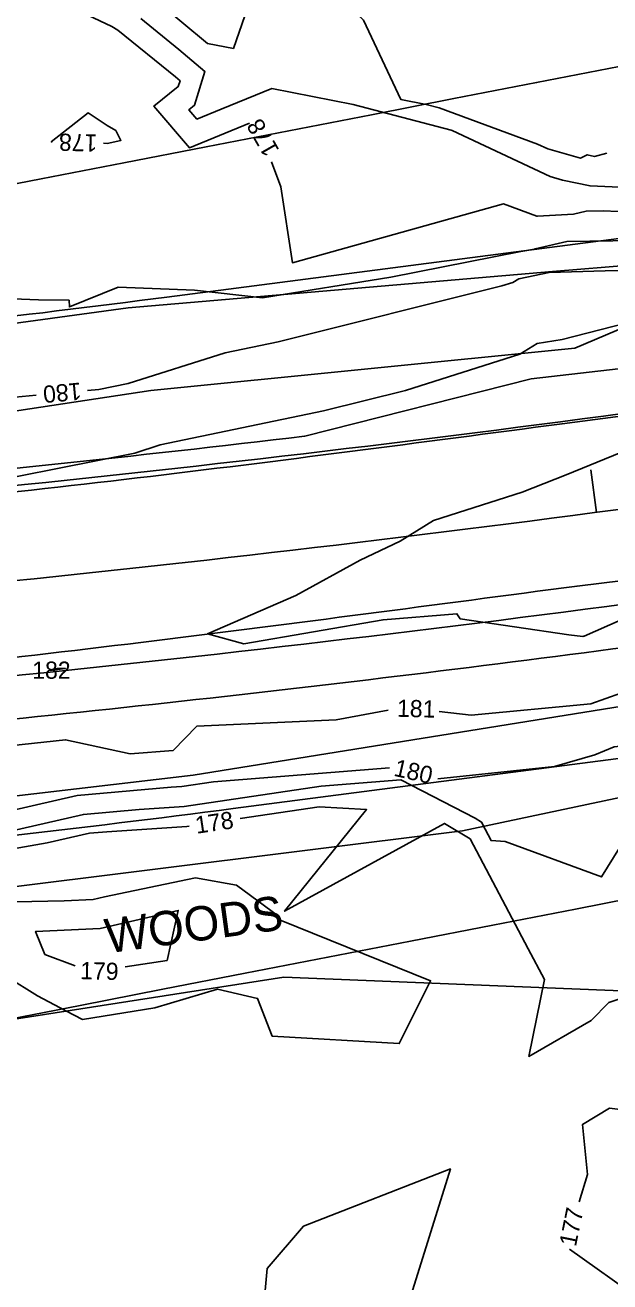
# Model space of a CAD drawing. Extents: x 2086416 to 2115205, y 575507 to 632762.
# Drawn here: x 2111355.3 to 2111423.3, y 581547.6 to 581693.8 of the extents above; entities that cross this region are included whole.
import ezdxf

# ---------------------------------------------------------------- set-up
doc = ezdxf.new("R2010")
doc.units = 0
for name, color, linetype in [('DTM Contours Major', 7, 'Continuous'), ('DTM Contours Major Text', 7, 'Continuous'), ('DTM Contours Minor', 7, 'Continuous'), ('DTM Contours Minor Text', 7, 'Continuous'), ('Exist Hydrographic FEMA Cross Section', 7, 'Continuous'), ('Exist Right of Way Line', 7, 'Continuous'), ('Exist Roads EOP', 7, 'Continuous'), ('Exist Vegetation Woods Line', 7, 'Continuous'), ('Exist Vegetation Woods Line Text', 7, 'Continuous'), ('Prop EOT', 7, 'Continuous'), ('Prop Horizontal Alignment', 7, 'Continuous'), ('Prop Horizontal Alignment Tick Small', 7, 'Continuous'), ('Prop Paved Shoulder', 7, 'Continuous'), ('Prop SS Fill Line', 7, 'Continuous')]:
    doc.layers.add(name, color=color, linetype=linetype)

msp = doc.modelspace()

# ---------------------------------------------------------------- linework, layer by layer
at = {"layer": 'DTM Contours Major'}
for points in [[(2111362.56, 581651.3), (2111363.86, 581651.42), (2111367.3, 581652.1), (2111378.59, 581655.68), (2111384.74, 581656.96), (2111410.78, 581663.46), (2111412.04, 581663.86), (2111412.76, 581664.3), (2111416.28, 581665.01), (2111422.79, 581665.2), (2111444.21, 581665.52), (2111445.08, 581665.48), (2111446.41, 581665.36), (2111460.73, 581665.47)], [(2111261.76, 581634.8), (2111264.49, 581635.02), (2111269.8, 581635.25), (2111274.63, 581635.79), (2111286.36, 581637), (2111296.9, 581639.48), (2111308.95, 581641.32), (2111310.89, 581644.07), (2111316.03, 581645.06), (2111318.27, 581646.08), (2111327.46, 581646.18), (2111327.64, 581649.21), (2111352.5, 581650.37), (2111356.59, 581650.74)], [(2111501.47, 581623.56), (2111493.7, 581622.18), (2111485.5, 581619.95), (2111473.32, 581616.45), (2111470.82, 581616.07), (2111467.71, 581615.67), (2111457.92, 581614.37), (2111451.07, 581613.49), (2111428.1, 581610.45), (2111427.71, 581610.26), (2111423.84, 581609.83), (2111421.6, 581608.92), (2111416.91, 581607.54), (2111403.3, 581606.12)], [(2111397.68, 581607.39), (2111377.21, 581605.77), (2111373.52, 581605.22), (2111372.31, 581605.14), (2111361.36, 581604.17), (2111347.99, 581601.11), (2111339.17, 581600.17), (2111336.15, 581600.07), (2111333.7, 581599.12), (2111322.16, 581599.48), (2111304, 581596.49), (2111303.23, 581596.59), (2111302.72, 581596.56), (2111299.03, 581595.67), (2111298.77, 581595.63)]]:
    msp.add_lwpolyline(points, dxfattribs=at)
at = {"layer": 'DTM Contours Minor'}
for points in [[(2111260.91, 581756.14), (2111260.56, 581753.66), (2111263.25, 581749.57), (2111272.06, 581734.37), (2111271.17, 581754.63), (2111289.23, 581762.28), (2111298.09, 581762.28), (2111340.41, 581719.17), (2111341.02, 581718.36), (2111341.03, 581718.18), (2111350.61, 581700.9), (2111351.45, 581700.22), (2111365.39, 581693.62), (2111366.1, 581693.23), (2111372.81, 581687.77), (2111373.33, 581687.33), (2111373.12, 581686.65), (2111370.29, 581684.39), (2111374.42, 581679.53), (2111381.41, 581682.41)], [(2111351.15, 581713.78), (2111355.49, 581705.96), (2111362.1, 581700.62), (2111366.93, 581698.33), (2111371.43, 581695.89), (2111373.55, 581694.16), (2111376.52, 581691.68), (2111379.54, 581691.09), (2111384.17, 581704.43), (2111394.67, 581694.38), (2111399.03, 581685.14), (2111401.95, 581684.57), (2111403.47, 581684.17), (2111414.91, 581679.96), (2111416.1, 581679.4), (2111419.93, 581678.31), (2111420.71, 581678.72), (2111421.55, 581678.53), (2111422.97, 581678.9)], [(2111368.76, 581694.56), (2111373.18, 581690.97), (2111376.21, 581688.42), (2111374.99, 581684.48), (2111374.35, 581683.96), (2111375.28, 581682.86), (2111378.11, 581684.03), (2111383.99, 581686.43), (2111393.45, 581684.58), (2111404.87, 581681.59), (2111405, 581681.54), (2111416.4, 581676.17), (2111417.82, 581675.76), (2111421.04, 581675.1), (2111426.98, 581674.84), (2111450.57, 581672.8), (2111451.55, 581672.81), (2111457.45, 581672.2), (2111464.43, 581672.63), (2111469.44, 581671.8), (2111479.52, 581672.4), (2111482.88, 581672.73), (2111491.53, 581672.68)], [(2111365.87, 581681.55), (2111364.85, 581682.14), (2111362.63, 581683.58), (2111358.35, 581680.21), (2111358.43, 581680.21)], [(2111364.43, 581680.05), (2111364.85, 581680.04), (2111366.44, 581680.38), (2111365.87, 581681.55)], [(2111383.97, 581677.91), (2111385.04, 581675), (2111386.4, 581666.15), (2111410.95, 581673), (2111414.82, 581671.57), (2111414.9, 581671.59), (2111419.09, 581671.8), (2111420.57, 581672.15), (2111422.55, 581672.18), (2111433.02, 581671.72)], [(2111317.9, 581663.35), (2111356.87, 581661.83), (2111360.41, 581661.79), (2111360.46, 581661.01), (2111366.13, 581663.3), (2111375, 581662.98), (2111382.9, 581662.08), (2111397.84, 581664.46), (2111412.99, 581667.48), (2111414.58, 581667.75), (2111414.66, 581667.76), (2111418.31, 581668.62), (2111431.74, 581668.82)], [(2111269.92, 581624.06), (2111270.71, 581624.17), (2111275.89, 581625.03), (2111295.14, 581628.3), (2111310.24, 581631.56), (2111319.39, 581633.41), (2111333.07, 581637.24), (2111339.35, 581639.05), (2111342.16, 581639.08), (2111342.18, 581639.38), (2111344.6, 581639.49), (2111345.71, 581639.59), (2111368.06, 581644.02), (2111371.03, 581644.96), (2111390.01, 581648.91), (2111399.54, 581651.29), (2111412.87, 581655.54), (2111414.88, 581656.76), (2111417.77, 581657.24), (2111425.19, 581659.11), (2111446.75, 581659.06), (2111455.96, 581661.78), (2111465.02, 581661.96)], [(2111428.2, 581645.56), (2111418.25, 581641.47), (2111413.14, 581639.46), (2111402.82, 581636.18), (2111398.93, 581633.78), (2111394.3, 581631.55), (2111386.79, 581627.45), (2111376.51, 581622.98), (2111380.73, 581621.81), (2111396.95, 581624.63), (2111405.53, 581625.33), (2111405.9, 581624.74), (2111418.54, 581622.87), (2111420.17, 581622.68), (2111420.32, 581622.7), (2111420.36, 581622.71), (2111424.64, 581624.62)], [(2111358.4, 581618.76), (2111358.22, 581618.75), (2111358.28, 581618.78), (2111359.02, 581618.95), (2111359.97, 581618.96), (2111358.47, 581618.75), (2111358.42, 581618.76), (2111358.4, 581618.76)], [(2111512.9, 581612.94), (2111502.54, 581616.24), (2111495.93, 581612.32), (2111495.05, 581609.68), (2111493.14, 581612.37), (2111486.49, 581613.5), (2111483.67, 581613.74), (2111483.2, 581613.6), (2111482.12, 581613.44), (2111472.63, 581599.99), (2111469.34, 581599.17), (2111466.84, 581596.07), (2111463.88, 581593.54), (2111423.2, 581580.1), (2111421.17, 581578.02), (2111413.92, 581573.83), (2111415.71, 581582.77), (2111413.83, 581586.35), (2111407.09, 581599.12), (2111404.08, 581600.93), (2111385.48, 581590.71), (2111395.03, 581602.54), (2111389.52, 581602.88), (2111380.32, 581601.49)], [(2111424.59, 581616.1), (2111421.12, 581614.85), (2111407.18, 581613.51), (2111403.49, 581613.94)], [(2111397.55, 581614.09), (2111391.47, 581612.99), (2111375.27, 581612.24), (2111372.52, 581609.42), (2111367.53, 581609.01), (2111360.01, 581610.67), (2111348.79, 581609.46)], [(2111438.65, 581609.75), (2111436.08, 581609.42), (2111428.87, 581608.47), (2111427.89, 581607.98), (2111428.68, 581604.78), (2111428.43, 581604.52), (2111422.37, 581594.71), (2111411.16, 581598.81), (2111409.52, 581598.94), (2111408.82, 581600.27), (2111408.4, 581601.08), (2111407.65, 581601.53), (2111399, 581606.02), (2111389.75, 581605.28), (2111373.81, 581602.89), (2111368.57, 581602.56), (2111362.09, 581601.98), (2111346.11, 581598.33)], [(2111374.39, 581600.6), (2111374.1, 581600.56), (2111364.82, 581599.97), (2111362.81, 581599.79), (2111357.86, 581598.66), (2111337.18, 581595.02)], [(2111348.47, 581591.69), (2111359.85, 581591.92), (2111363.21, 581592.07), (2111364.55, 581592.38), (2111375.14, 581594.6), (2111379.9, 581593.75), (2111384.79, 581590.13), (2111384.8, 581590.02), (2111384.91, 581589.73), (2111402.48, 581582.63), (2111398.82, 581575.32), (2111384.06, 581576.17), (2111382.35, 581580.57), (2111377.7, 581581.64), (2111370.4, 581579.47), (2111361.98, 581578.12), (2111360.04, 581579.14), (2111356.74, 581580.89), (2111353.12, 581583.13)], [(2111364.04, 581588.72), (2111373.11, 581590.81), (2111371.82, 581585), (2111366.95, 581584.23)], [(2111361.14, 581584.38), (2111357.61, 581585.69), (2111356.52, 581588.37), (2111364.04, 581588.72)], [(2111460.9, 581557.08), (2111444.39, 581560.24), (2111437.91, 581565.95), (2111423.3, 581567.8), (2111420.16, 581565.92), (2111420.73, 581560.08), (2111419.75, 581556.92)], [(2111400.04, 581545.48), (2111404.78, 581560.74), (2111387.67, 581554.07), (2111383.48, 581549.16), (2111382.97, 581543.66), (2111367.99, 581529.18), (2111362.31, 581526.33), (2111380.49, 581503.83), (2111377.38, 581495.42), (2111386.55, 581494.27), (2111406.58, 581457.51), (2111416.51, 581491.31), (2111416.75, 581493.56)], [(2111418.62, 581551.41), (2111426.83, 581545.6), (2111432.28, 581544.28), (2111460.9, 581557.08)]]:
    msp.add_lwpolyline(points, dxfattribs=at)
at = {"layer": 'Exist Hydrographic FEMA Cross Section'}
for points in [[(2111558.92, 581715.13), (2111549.31, 581713.26), (2111539.7, 581711.4), (2111530.09, 581709.53), (2111520.48, 581707.66), (2111510.88, 581705.79), (2111501.27, 581703.93), (2111491.66, 581702.06), (2111482.06, 581700.19), (2111472.45, 581698.32), (2111462.84, 581696.46), (2111453.23, 581694.59), (2111443.62, 581692.72), (2111434.02, 581690.85), (2111424.41, 581688.98), (2111414.8, 581687.11), (2111405.19, 581685.25), (2111395.59, 581683.38), (2111385.98, 581681.51), (2111376.37, 581679.64), (2111366.77, 581677.77), (2111357.16, 581675.91), (2111347.55, 581674.04)], [(2111658.78, 581615.59), (2111477.28, 581602.23), (2111476.99, 581602.18), (2111467.38, 581600.31), (2111457.77, 581598.44), (2111448.17, 581596.57), (2111438.56, 581594.71), (2111428.95, 581592.84), (2111419.34, 581590.97), (2111409.73, 581589.1), (2111400.13, 581587.23), (2111390.52, 581585.36), (2111380.91, 581583.5), (2111371.31, 581581.63), (2111361.7, 581579.76), (2111352.09, 581577.89)]]:
    msp.add_lwpolyline(points, dxfattribs=at)
at = {"layer": 'Exist Right of Way Line'}
for points in [[(2111371.8, 581662.16), (2111512.52, 581680.42)], [(2111379.52, 581602.66), (2111520.24, 581620.92)]]:
    msp.add_lwpolyline(points, dxfattribs=at)
for radius in [1658.19, 1718.19]:
    msp.add_arc((2111158.41, 583306.56), radius, 273.81807, 277.39391, dxfattribs=at)
at = {"layer": 'Exist Roads EOP'}
for points in [[(2111417.78, 581647.42), (2111417.78, 581647.42), (2111466.25, 581653.76), (2111515.09, 581660.44), (2111516.54, 581650.63)], [(2111419.52, 581628.55), (2111419.52, 581628.55), (2111468.66, 581634.58), (2111518, 581640.73), (2111516.54, 581650.63)]]:
    msp.add_lwpolyline(points, dxfattribs=at)
for points in [[(2110977.48, 581650.48), (2111025.79, 581641.84), (2111074.55, 581635.25), (2111123.2, 581631.18), (2111172.22, 581629.18), (2111221.29, 581629.52), (2111270.17, 581631.7), (2111319.13, 581635.84), (2111368.33, 581641.12), (2111417.78, 581647.42)], [(2110973.54, 581631.44), (2111022.55, 581622.76), (2111072.45, 581615.95), (2111122.07, 581611.59), (2111171.98, 581610.01), (2111221.99, 581610.11), (2111271.48, 581612.54), (2111320.96, 581616.67), (2111370.32, 581622.18), (2111419.52, 581628.55)]]:
    msp.add_spline(points, degree=3, dxfattribs=at)
at = {"layer": 'Exist Vegetation Woods Line'}
for points in [[(2111452.1, 581736.22), (2111479.27, 581697.5), (2111499.68, 581677.78), (2111492.04, 581671.34), (2111416.64, 581665.13), (2111367.28, 581660.93), (2111318.17, 581654.2), (2111268.32, 581650.61), (2111220.66, 581649.45), (2111173.29, 581649.12), (2111125.98, 581651.57), (2111078.27, 581655.72), (2111059.79, 581657.65)], [(2111257.87, 581581.4), (2111333.1, 581590.97), (2111406.18, 581600.07), (2111473.94, 581614.42), (2111501.63, 581613.42), (2111525.04, 581604.65), (2111555.79, 581590.73), (2111597.41, 581531.02), (2111635.4, 581485.12), (2111692.38, 581438.81), (2111736.92, 581397.7), (2111757.96, 581379.06)], [(2111566.76, 581548.29), (2111551.99, 581576.31), (2111385.4, 581583.05), (2111297.09, 581569.27), (2111253.55, 581562.72), (2111242.01, 581577.17), (2111257.87, 581581.4)]]:
    msp.add_lwpolyline(points, dxfattribs=at)
at = {"layer": 'Prop EOT'}
for radius in [2331.03, 2353.03]:
    msp.add_arc((2111114.87, 583958.95), radius, 273.81807, 277.77101, dxfattribs=at)
at = {"layer": 'Prop Horizontal Alignment'}
msp.add_arc((2111114.87, 583958.95), 2342.03, 273.81807, 277.77101, dxfattribs=at)
at = {"layer": 'Prop Horizontal Alignment Tick Small'}
msp.add_line((2111421.78, 581637.12), (2111421.12, 581642.07), dxfattribs=at)
at = {"layer": 'Prop Paved Shoulder'}
for p, q in [((2111463.75, 581658.38), (2111414.17, 581652.66)), ((2111414.17, 581652.66), (2111387.83, 581645.97))]:
    msp.add_line(p, q, dxfattribs=at)
for radius, start, end in [(2329.03, 273.81807, 276.73016), (2358.03, 275.14998, 277.77101)]:
    msp.add_arc((2111114.87, 583958.95), radius, start, end, dxfattribs=at)
at = {"layer": 'Prop SS Fill Line'}
for p, q in [((2111419.26, 581656.2), (2111481.21, 581682.79)), ((2111369.91, 581651.29), (2111419.26, 581656.2)), ((2111320.81, 581643.91), (2111369.91, 581651.29)), ((2111374.86, 581606.53), (2111424.76, 581614.57)), ((2111324.66, 581600.66), (2111374.86, 581606.53))]:
    msp.add_line(p, q, dxfattribs=at)

# ---------------------------------------------------------------- texts
at = {"layer": 'DTM Contours Major Text'}
for rotation, p in [(185.2883, (2111361.75, 581652.23)), (347.1777, (2111398.09, 581606.49))]:
    msp.add_text('180', height=2, rotation=rotation, dxfattribs=at).set_placement(p)
at = {"layer": 'DTM Contours Minor Text'}
for s, rotation, p in [('178', 119.6875, (2111384.93, 581679.25)), ('178', 178.5046, (2111363.73, 581681.07)), ('181', 358.626, (2111398.55, 581613.34)), ('178', 8.5465, (2111375.25, 581599.72)), ('179', 358.5805, (2111361.69, 581582.82)), ('177', 78.4527, (2111419.38, 581551.62))]:
    msp.add_text(s, height=2, rotation=rotation, dxfattribs=at).set_placement(p)
msp.add_text('182', height=2, dxfattribs=at).set_placement((2111356.13, 581617.76))
at = {"layer": 'Exist Vegetation Woods Line Text'}
msp.add_text('WOODS', height=4, rotation=7.771, dxfattribs=at).set_placement((2111364.89, 581585.81))

doc.saveas('drawing.dxf')
